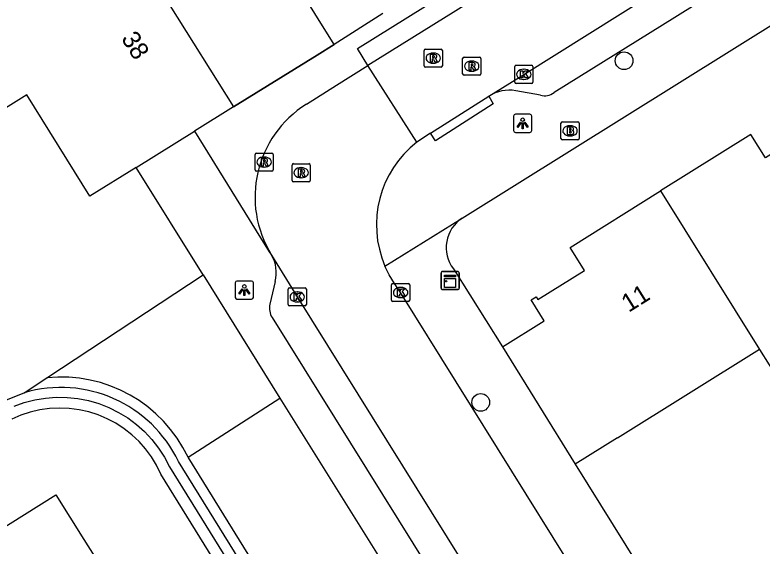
# Model space of a CAD drawing. Extents: x 158838 to 160074, y 386376 to 387776.
# Drawn here: x 159038.51 to 159079.75, y 387026.31 to 387055.6 of the extents above; entities that cross this region are included whole.
import ezdxf

# ---------------------------------------------------------------- set-up
doc = ezdxf.new("R2010")
doc.units = 0
for name, color, linetype in [('IMGEO_Boom', 7, 'Continuous'), ('IMGEO_Brandkraan', 7, 'Continuous'), ('IMGEO_Groenvoorziening', 7, 'Continuous'), ('IMGEO_Hek', 7, 'Continuous'), ('IMGEO_Kast', 7, 'Continuous'), ('IMGEO_Kolk', 7, 'Continuous'), ('IMGEO_Lichtpunt', 7, 'Continuous'), ('IMGEO_Loofbos', 7, 'Continuous'), ('IMGEO_Muur', 7, 'Continuous'), ('IMGEO_Pand', 7, 'Continuous'), ('IMGEO_Pand_nummerreeks', 7, 'Continuous'), ('IMGEO_Rijbaan_lokaal_gesloten', 7, 'Continuous'), ('IMGEO_Rijbaan_lokaal_open', 7, 'Continuous'), ('IMGEO_Rioolput', 7, 'Continuous'), ('IMGEO_Voetpad_open', 7, 'Continuous')]:
    doc.layers.add(name, color=color, linetype=linetype)

msp = doc.modelspace()

# ---------------------------------------------------------------- linework, layer by layer
at = {"layer": 'IMGEO_Boom'}
for centre in [(159072.133, 387053.077), (159064.221, 387034.233)]:
    msp.add_circle(centre, 0.489, dxfattribs=at)
at = {"layer": 'IMGEO_Brandkraan'}
for p, q in [((159068.649, 387048.786), (159068.649, 387049.638)), ((159068.724, 387049.712), (159069.576, 387049.712)), ((159069.137, 387049.492), (159069.162, 387049.492)), ((159069.65, 387049.638), (159069.65, 387048.786)), ((159069.576, 387048.712), (159068.724, 387048.712)), ((159069.16, 387048.932), (159069.135, 387048.932))]:
    msp.add_line(p, q, dxfattribs=at)
for points in [[(159068.649, 387048.786), (159068.649, 387049.638)], [(159068.724, 387049.712), (159069.576, 387049.712)], [(159069.65, 387049.638), (159069.65, 387048.786)], [(159068.997, 387049.412), (159068.997, 387049.012), (159069.21, 387049.012)], [(159069.228, 387049.412), (159068.997, 387049.412)], [(159069.176, 387049.331), (159069.122, 387049.331), (159069.122, 387049.255)], [(159069.122, 387049.255), (159069.175, 387049.255)], [(159069.184, 387049.179), (159069.122, 387049.179), (159069.122, 387049.098)], [(159069.122, 387049.098), (159069.184, 387049.098)], [(159069.576, 387048.712), (159068.724, 387048.712)]]:
    msp.add_lwpolyline(points, dxfattribs=at)
for centre, radius, start, end in [((159068.726, 387049.636), 0.0765, 91.552, 178.448), ((159068.726, 387049.636), 0.0765, 91.552, 178.448), ((159069.574, 387049.636), 0.0765, 1.552, 88.448), ((159069.574, 387049.636), 0.0765, 1.552, 88.448), ((159069.177, 387049.293), 0.0379, 267.8285, 90.9355), ((159069.185, 387049.138), 0.0404, 269.8759, 90.5077), ((159069.216, 387049.263), 0.251, 268.6676, 293.5347), ((159069.232, 387049.267), 0.145, 59.4692, 91.5367), ((159069.257, 387049.314), 0.0922, 285.5137, 58.1501), ((159069.262, 387049.122), 0.105, 301.3115, 78.989), ((159068.726, 387048.788), 0.0765, 181.552, 268.448), ((159068.726, 387048.788), 0.0765, 181.552, 268.448), ((159069.574, 387048.788), 0.0765, 271.552, 358.448), ((159069.574, 387048.788), 0.0765, 271.552, 358.448)]:
    msp.add_arc(centre, radius, start, end, dxfattribs=at)
for centre, major_axis, ratio, start_param, end_param in [((159069.136, 387049.212), (-0.387, 0.002), 0.722429, 4.712389, 7.853982), ((159069.161, 387049.212), (-0.39, 0.002), 0.717154, 1.570796, 4.712389)]:
    msp.add_ellipse(centre, major_axis=major_axis, ratio=ratio, start_param=start_param, end_param=end_param, dxfattribs=at)
at = {"layer": 'IMGEO_Groenvoorziening'}
for points in [[(159040.266, 387035.588), (159048.898, 387041.261)], [(159039.016, 387034.766), (159040.266, 387035.588)], [(159033.552, 387032.261), (159037.206, 387034.045), (159039.016, 387034.766)], [(159038.465, 387034.016), (159039.026, 387034.218), (159039.604, 387034.369), (159040.193, 387034.467), (159040.788, 387034.513), (159041.385, 387034.505), (159041.979, 387034.444), (159042.565, 387034.33), (159043.139, 387034.164), (159043.695, 387033.948), (159044.23, 387033.683), (159044.739, 387033.371), (159045.219, 387033.015), (159045.664, 387032.617), (159046.072, 387032.181), (159046.44, 387031.711), (159046.764, 387031.209), (159047.042, 387030.681), (159066.053, 387000)], [(159048.064, 387031.206), (159053.135, 387034.473)], [(159110.881, 386928.808), (159066.743, 387000), (159047.544, 387030.967)], [(159057.059, 387016.709), (159048.064, 387031.206)]]:
    msp.add_lwpolyline(points, dxfattribs=at)
for centre, radius, start, end in [((159041.075, 387027.898), 7.732, 25.328, 96.0053), ((159041.036, 387027.83), 7.225, 25.739, 106.2375)]:
    msp.add_arc(centre, radius, start, end, dxfattribs=at)
at = {"layer": 'IMGEO_Hek'}
msp.add_lwpolyline([(159039.016, 387034.766), (159040.266, 387035.588)], dxfattribs=at)
at = {"layer": 'IMGEO_Kast'}
for p, q in [((159062.029, 387040.525), (159062.029, 387041.366)), ((159062.029, 387041.366), (159062.029, 387040.525)), ((159062.104, 387041.45), (159062.945, 387041.45)), ((159062.945, 387041.45), (159062.104, 387041.45)), ((159063.029, 387041.375), (159063.029, 387040.534)), ((159063.029, 387040.534), (159063.029, 387041.375)), ((159062.954, 387040.45), (159062.113, 387040.45)), ((159062.113, 387040.45), (159062.954, 387040.45))]:
    msp.add_line(p, q, dxfattribs=at)
for points in [[(159062.224, 387041.24), (159062.824, 387041.24), (159062.824, 387041.155), (159062.224, 387041.155), (159062.224, 387041.24)], [(159062.224, 387041.065), (159062.824, 387041.065), (159062.824, 387040.576), (159062.224, 387040.576), (159062.224, 387041.065)]]:
    msp.add_lwpolyline(points, dxfattribs=at)
msp.add_circle((159062.308, 387040.914), 0.0377, dxfattribs=at)
for centre, start, end in [((159062.107, 387041.372), 92.4484, 184.2845), ((159062.107, 387041.372), 92.4484, 184.2845), ((159062.951, 387041.372), 2.4484, 94.2845), ((159062.951, 387041.372), 2.4484, 94.2845), ((159062.107, 387040.528), 182.4484, 274.2845), ((159062.107, 387040.528), 182.4484, 274.2845), ((159062.951, 387040.528), 272.4484, 4.2845), ((159062.951, 387040.528), 272.4484, 4.2845)]:
    msp.add_arc(centre, 0.0779, start, end, dxfattribs=at)
at = {"layer": 'IMGEO_Kolk'}
for p, q in [((159066.096, 387051.899), (159066.096, 387052.751)), ((159066.171, 387052.825), (159067.023, 387052.825)), ((159067.097, 387052.751), (159067.097, 387051.899)), ((159066.584, 387052.605), (159066.609, 387052.605)), ((159066.607, 387052.045), (159066.582, 387052.045)), ((159067.023, 387051.825), (159066.171, 387051.825)), ((159059.375, 387040.79), (159060.227, 387040.79)), ((159053.595, 387039.623), (159053.595, 387040.475)), ((159053.67, 387040.549), (159054.522, 387040.549)), ((159054.596, 387040.475), (159054.596, 387039.623)), ((159059.3, 387039.864), (159059.3, 387040.716)), ((159059.788, 387040.57), (159059.813, 387040.57)), ((159060.301, 387040.716), (159060.301, 387039.864)), ((159054.083, 387040.329), (159054.108, 387040.329)), ((159059.811, 387040.01), (159059.786, 387040.01)), ((159054.522, 387039.549), (159053.67, 387039.549)), ((159054.106, 387039.769), (159054.081, 387039.769)), ((159060.227, 387039.79), (159059.375, 387039.79))]:
    msp.add_line(p, q, dxfattribs=at)
for points in [[(159066.096, 387051.899), (159066.096, 387052.751)], [(159066.171, 387052.825), (159067.023, 387052.825)], [(159067.097, 387052.751), (159067.097, 387051.899)], [(159066.417, 387052.525), (159066.54, 387052.525), (159066.54, 387052.374), (159066.67, 387052.525), (159066.834, 387052.525), (159066.688, 387052.374), (159066.841, 387052.125), (159066.689, 387052.125), (159066.604, 387052.289), (159066.54, 387052.222), (159066.54, 387052.125), (159066.417, 387052.125), (159066.417, 387052.525)], [(159067.023, 387051.825), (159066.171, 387051.825)], [(159059.375, 387040.79), (159060.227, 387040.79)], [(159053.595, 387039.623), (159053.595, 387040.475)], [(159053.67, 387040.549), (159054.522, 387040.549)], [(159054.596, 387040.475), (159054.596, 387039.623)], [(159059.3, 387039.864), (159059.3, 387040.716)], [(159059.621, 387040.49), (159059.744, 387040.49), (159059.744, 387040.339), (159059.874, 387040.49), (159060.038, 387040.49), (159059.892, 387040.339), (159060.045, 387040.09), (159059.893, 387040.09), (159059.808, 387040.254), (159059.744, 387040.187), (159059.744, 387040.09), (159059.621, 387040.09), (159059.621, 387040.49)], [(159060.301, 387040.716), (159060.301, 387039.864)], [(159053.916, 387040.249), (159054.039, 387040.249), (159054.039, 387040.098), (159054.169, 387040.249), (159054.333, 387040.249), (159054.187, 387040.098), (159054.34, 387039.849), (159054.188, 387039.849), (159054.103, 387040.013), (159054.039, 387039.946), (159054.039, 387039.849), (159053.916, 387039.849), (159053.916, 387040.249)], [(159054.522, 387039.549), (159053.67, 387039.549)], [(159060.227, 387039.79), (159059.375, 387039.79)]]:
    msp.add_lwpolyline(points, dxfattribs=at)
for centre, start, end in [((159066.173, 387052.749), 91.552, 178.448), ((159066.173, 387052.749), 91.552, 178.448), ((159067.021, 387052.749), 1.552, 88.448), ((159067.021, 387052.749), 1.552, 88.448), ((159066.173, 387051.901), 181.552, 268.448), ((159066.173, 387051.901), 181.552, 268.448), ((159067.021, 387051.901), 271.552, 358.448), ((159067.021, 387051.901), 271.552, 358.448), ((159059.377, 387040.714), 91.552, 178.448), ((159059.377, 387040.714), 91.552, 178.448), ((159060.225, 387040.714), 1.552, 88.448), ((159060.225, 387040.714), 1.552, 88.448), ((159053.672, 387040.473), 91.552, 178.448), ((159053.672, 387040.473), 91.552, 178.448), ((159054.52, 387040.473), 1.552, 88.448), ((159054.52, 387040.473), 1.552, 88.448), ((159053.672, 387039.625), 181.552, 268.448), ((159053.672, 387039.625), 181.552, 268.448), ((159054.52, 387039.625), 271.552, 358.448), ((159054.52, 387039.625), 271.552, 358.448), ((159059.377, 387039.866), 181.552, 268.448), ((159059.377, 387039.866), 181.552, 268.448), ((159060.225, 387039.866), 271.552, 358.448), ((159060.225, 387039.866), 271.552, 358.448)]:
    msp.add_arc(centre, 0.0765, start, end, dxfattribs=at)
for centre, major_axis, ratio, start_param, end_param in [((159066.583, 387052.325), (-0.387, 0.002), 0.722429, 4.712389, 7.853982), ((159066.608, 387052.325), (-0.39, 0.002), 0.717154, 1.570796, 4.712389), ((159059.787, 387040.29), (-0.387, 0.002), 0.722429, 4.712389, 7.853982), ((159059.812, 387040.29), (-0.39, 0.002), 0.717154, 1.570796, 4.712389), ((159054.082, 387040.049), (-0.387, 0.002), 0.722429, 4.712389, 7.853982), ((159054.107, 387040.049), (-0.39, 0.002), 0.717154, 1.570796, 4.712389)]:
    msp.add_ellipse(centre, major_axis=major_axis, ratio=ratio, start_param=start_param, end_param=end_param, dxfattribs=at)
at = {"layer": 'IMGEO_Lichtpunt'}
for p, q in [((159066.037, 387050.028), (159066.037, 387049.221)), ((159066.037, 387050.028), (159066.037, 387049.221)), ((159066.939, 387050.123), (159066.131, 387050.123)), ((159066.939, 387050.123), (159066.131, 387050.123)), ((159067.033, 387049.221), (159067.033, 387050.028)), ((159067.033, 387049.221), (159067.033, 387050.028)), ((159066.131, 387049.127), (159066.939, 387049.127)), ((159066.131, 387049.127), (159066.939, 387049.127)), ((159050.674, 387040.83), (159050.674, 387040.023)), ((159050.674, 387040.83), (159050.674, 387040.023)), ((159051.576, 387040.925), (159050.768, 387040.925)), ((159051.576, 387040.925), (159050.768, 387040.925)), ((159051.67, 387040.023), (159051.67, 387040.83)), ((159051.67, 387040.023), (159051.67, 387040.83)), ((159050.768, 387039.929), (159051.576, 387039.929)), ((159050.768, 387039.929), (159051.576, 387039.929))]:
    msp.add_line(p, q, dxfattribs=at)
for points in [[(159066.411, 387049.692), (159066.45, 387049.664), (159066.262, 387049.402), (159066.224, 387049.429), (159066.411, 387049.692)], [(159066.513, 387049.644), (159066.56, 387049.644), (159066.56, 387049.322), (159066.513, 387049.322), (159066.513, 387049.644)], [(159066.623, 387049.664), (159066.661, 387049.691), (159066.848, 387049.429), (159066.809, 387049.401), (159066.623, 387049.664)], [(159051.048, 387040.494), (159051.087, 387040.466), (159050.899, 387040.204), (159050.861, 387040.231), (159051.048, 387040.494)], [(159051.15, 387040.446), (159051.197, 387040.446), (159051.197, 387040.124), (159051.15, 387040.124), (159051.15, 387040.446)], [(159051.26, 387040.466), (159051.298, 387040.493), (159051.485, 387040.231), (159051.446, 387040.203), (159051.26, 387040.466)]]:
    msp.add_lwpolyline(points, dxfattribs=at)
for centre in [(159066.536, 387049.826), (159051.173, 387040.628)]:
    msp.add_circle(centre, 0.0994, dxfattribs=at)
for centre, start, end in [((159066.131, 387050.028), 90, 180), ((159066.131, 387050.028), 90, 180), ((159066.939, 387050.028), 0, 90), ((159066.939, 387050.028), 0, 90), ((159066.131, 387049.221), 180, 270), ((159066.131, 387049.221), 180, 270), ((159066.939, 387049.221), 270, 0), ((159066.939, 387049.221), 270, 360), ((159050.768, 387040.83), 90, 180), ((159050.768, 387040.83), 90, 180), ((159051.576, 387040.83), 0, 90), ((159051.576, 387040.83), 0, 90), ((159050.768, 387040.023), 180, 270), ((159050.768, 387040.023), 180, 270), ((159051.576, 387040.023), 270, 0), ((159051.576, 387040.023), 270, 360)]:
    msp.add_arc(centre, 0.0946, start, end, dxfattribs=at)
at = {"layer": 'IMGEO_Loofbos'}
for points in [[(159065.319, 387000), (159046.571, 387030.271), (159046.331, 387030.76), (159046.048, 387031.225), (159045.724, 387031.663), (159045.363, 387032.07), (159044.967, 387032.444), (159044.539, 387032.78), (159044.082, 387033.078), (159043.601, 387033.333), (159043.099, 387033.544), (159042.581, 387033.709), (159042.049, 387033.828), (159041.509, 387033.898), (159040.965, 387033.92), (159040.421, 387033.893), (159039.882, 387033.818), (159039.352, 387033.695), (159038.834, 387033.525), (159038.334, 387033.309)], [(159027.668, 387025.411), (159031.623, 387024.617), (159033.066, 387024.328), (159037.285, 387026.957), (159040.771, 387029.129), (159042.317, 387026.665), (159042.882, 387025.766), (159059.05, 387000), (159105.278, 386926.65)]]:
    msp.add_lwpolyline(points, dxfattribs=at)
at = {"layer": 'IMGEO_Muur'}
for points in [[(159055.192, 387053.386), (159056.14, 387053.974)], [(159050.577, 387050.525), (159055.192, 387053.386)], [(159069.441, 387030.819), (159076.524, 387019.468)]]:
    msp.add_lwpolyline(points, dxfattribs=at)
at = {"layer": 'IMGEO_Pand'}
for points in [[(159044.387, 387060.389), (159045.439, 387061.047), (159048.113, 387056.775), (159047.067, 387056.119), (159050.577, 387050.525)], [(159045.198, 387047.189), (159042.642, 387045.603), (159039.161, 387051.19), (159027.496, 387043.921), (159024.821, 387048.202), (159036.538, 387055.521)], [(159050.577, 387050.525), (159048.428, 387049.192)], [(159045.198, 387047.189), (159048.428, 387049.192)], [(159082.578, 387049.382), (159079.934, 387047.727), (159079.133, 387049.006), (159074.14, 387045.892)], [(159065.419, 387037.291), (159067.725, 387038.732), (159067.005, 387039.886), (159067.275, 387040.054), (159067.37, 387039.902), (159069.951, 387041.51), (159069.158, 387042.784), (159074.14, 387045.892)], [(159074.14, 387045.892), (159079.6, 387037.141)], [(159079.6, 387037.141), (159081.208, 387034.61), (159088.84, 387039.38), (159087.251, 387041.923)], [(159065.419, 387037.291), (159069.441, 387030.819)], [(159079.6, 387037.141), (159071.774, 387032.25), (159071.762, 387032.269), (159069.441, 387030.819)]]:
    msp.add_lwpolyline(points, dxfattribs=at)
at = {"layer": 'IMGEO_Rijbaan_lokaal_gesloten'}
for points in [[(159054.603, 387050.681), (159056.255, 387051.72), (159057.993, 387052.813)], [(159060.695, 387048.588), (159057.993, 387052.813)], [(159052.677, 387042.36), (159054.093, 387040.05), (159064.841, 387022.833), (159075.554, 387005.639), (159079.076, 387000), (159097.478, 386970.538), (159108.751, 386952.473), (159118.667, 386936.572)], [(159074.471, 387016.785), (159069.014, 387025.517), (159059.796, 387040.289), (159059.457, 387040.794), (159059.172, 387041.262), (159058.932, 387041.754)]]:
    msp.add_lwpolyline(points, dxfattribs=at)
for centre, radius, start, end in [((159057.805, 387045.556), 6.043, 121.9995, 211.9359), ((159064.237, 387044.03), 5.773, 127.8497, 203.2194)]:
    msp.add_arc(centre, radius, start, end, dxfattribs=at)
at = {"layer": 'IMGEO_Rijbaan_lokaal_open'}
for points in [[(159064.66, 387051.128), (159066.593, 387052.325), (159084.528, 387063.55), (159103.151, 387075.188), (159110.593, 387079.859)], [(159066.482, 387058.108), (159057.993, 387052.813)], [(159061.454, 387049.086), (159064.66, 387051.128)], [(159061.454, 387049.086), (159060.695, 387048.588)]]:
    msp.add_lwpolyline(points, dxfattribs=at)
at = {"layer": 'IMGEO_Rioolput'}
for p, q in [((159061.101, 387052.794), (159061.101, 387053.646)), ((159061.176, 387053.72), (159062.028, 387053.72)), ((159062.102, 387053.646), (159062.102, 387052.794)), ((159061.589, 387053.5), (159061.614, 387053.5)), ((159063.223, 387052.351), (159063.223, 387053.203)), ((159063.298, 387053.277), (159064.15, 387053.277)), ((159064.224, 387053.203), (159064.224, 387052.351)), ((159062.028, 387052.72), (159061.176, 387052.72)), ((159061.612, 387052.94), (159061.587, 387052.94)), ((159063.711, 387053.057), (159063.736, 387053.057)), ((159063.734, 387052.497), (159063.709, 387052.497)), ((159064.15, 387052.277), (159063.298, 387052.277)), ((159051.762, 387047.061), (159051.762, 387047.913)), ((159051.837, 387047.987), (159052.689, 387047.987)), ((159052.25, 387047.767), (159052.275, 387047.767)), ((159052.763, 387047.913), (159052.763, 387047.061)), ((159053.883, 387047.399), (159054.735, 387047.399)), ((159052.689, 387046.987), (159051.837, 387046.987)), ((159052.273, 387047.207), (159052.248, 387047.207)), ((159053.808, 387046.473), (159053.808, 387047.325)), ((159054.296, 387047.179), (159054.321, 387047.179)), ((159054.809, 387047.325), (159054.809, 387046.473)), ((159054.319, 387046.619), (159054.294, 387046.619)), ((159054.735, 387046.399), (159053.883, 387046.399))]:
    msp.add_line(p, q, dxfattribs=at)
for points in [[(159061.101, 387052.794), (159061.101, 387053.646)], [(159061.176, 387053.72), (159062.028, 387053.72)], [(159062.102, 387053.646), (159062.102, 387052.794)], [(159061.69, 387053.418), (159061.438, 387053.42), (159061.438, 387053.02)], [(159061.438, 387053.02), (159061.562, 387053.02), (159061.562, 387053.182), (159061.573, 387053.182)], [(159061.616, 387053.339), (159061.562, 387053.339), (159061.562, 387053.258)], [(159061.562, 387053.258), (159061.614, 387053.258)], [(159061.62, 387053.153), (159061.691, 387053.02), (159061.831, 387053.02), (159061.766, 387053.146)], [(159063.223, 387052.351), (159063.223, 387053.203)], [(159063.298, 387053.277), (159064.15, 387053.277)], [(159064.224, 387053.203), (159064.224, 387052.351)], [(159062.028, 387052.72), (159061.176, 387052.72)], [(159063.812, 387052.975), (159063.56, 387052.977), (159063.56, 387052.577)], [(159063.56, 387052.577), (159063.684, 387052.577), (159063.684, 387052.739), (159063.695, 387052.739)], [(159063.738, 387052.896), (159063.684, 387052.896), (159063.684, 387052.815)], [(159063.684, 387052.815), (159063.736, 387052.815)], [(159063.742, 387052.71), (159063.813, 387052.577), (159063.953, 387052.577), (159063.888, 387052.703)], [(159064.15, 387052.277), (159063.298, 387052.277)], [(159051.762, 387047.061), (159051.762, 387047.913)], [(159051.837, 387047.987), (159052.689, 387047.987)], [(159052.763, 387047.913), (159052.763, 387047.061)], [(159052.351, 387047.685), (159052.099, 387047.687), (159052.099, 387047.287)], [(159052.099, 387047.287), (159052.223, 387047.287), (159052.223, 387047.449), (159052.234, 387047.449)], [(159052.277, 387047.606), (159052.223, 387047.606), (159052.223, 387047.525)], [(159052.223, 387047.525), (159052.275, 387047.525)], [(159052.281, 387047.42), (159052.352, 387047.287), (159052.492, 387047.287), (159052.427, 387047.413)], [(159053.883, 387047.399), (159054.735, 387047.399)], [(159052.689, 387046.987), (159051.837, 387046.987)], [(159053.808, 387046.473), (159053.808, 387047.325)], [(159054.397, 387047.097), (159054.145, 387047.099), (159054.145, 387046.699)], [(159054.323, 387047.018), (159054.269, 387047.018), (159054.269, 387046.937)], [(159054.809, 387047.325), (159054.809, 387046.473)], [(159054.145, 387046.699), (159054.269, 387046.699), (159054.269, 387046.861), (159054.28, 387046.861)], [(159054.269, 387046.937), (159054.321, 387046.937)], [(159054.327, 387046.832), (159054.398, 387046.699), (159054.538, 387046.699), (159054.473, 387046.825)], [(159054.735, 387046.399), (159053.883, 387046.399)]]:
    msp.add_lwpolyline(points, dxfattribs=at)
for centre, radius, start, end in [((159061.178, 387053.644), 0.0765, 91.552, 178.448), ((159061.178, 387053.644), 0.0765, 91.552, 178.448), ((159062.026, 387053.644), 0.0765, 1.552, 88.448), ((159062.026, 387053.644), 0.0765, 1.552, 88.448), ((159061.572, 387053.129), 0.0533, 26.0293, 88.6989), ((159061.598, 387053.447), 0.19, 274.7715, 282.9687), ((159061.622, 387053.243), 0.0964, 77.0061, 93.1865), ((159061.636, 387053.3), 0.0378, 276.6634, 79.6772), ((159061.689, 387053.308), 0.109, 350.3612, 89.416), ((159061.687, 387053.308), 0.112, 277.5842, 350.9817), ((159061.671, 387053.093), 0.108, 29.5134, 73.7905), ((159063.3, 387053.201), 0.0765, 91.552, 178.448), ((159063.3, 387053.201), 0.0765, 91.552, 178.448), ((159064.148, 387053.201), 0.0765, 1.552, 88.448), ((159064.148, 387053.201), 0.0765, 1.552, 88.448), ((159061.178, 387052.796), 0.0765, 181.552, 268.448), ((159061.178, 387052.796), 0.0765, 181.552, 268.448), ((159062.026, 387052.796), 0.0765, 271.552, 358.448), ((159062.026, 387052.796), 0.0765, 271.552, 358.448), ((159063.694, 387052.686), 0.0533, 26.0293, 88.6989), ((159063.72, 387053.004), 0.19, 274.7715, 282.9687), ((159063.744, 387052.8), 0.0964, 77.0061, 93.1865), ((159063.758, 387052.857), 0.0378, 276.6634, 79.6772), ((159063.811, 387052.865), 0.109, 350.3612, 89.416), ((159063.809, 387052.865), 0.112, 277.5842, 350.9817), ((159063.793, 387052.65), 0.108, 29.5134, 73.7905), ((159063.3, 387052.353), 0.0765, 181.552, 268.448), ((159063.3, 387052.353), 0.0765, 181.552, 268.448), ((159064.148, 387052.353), 0.0765, 271.552, 358.448), ((159064.148, 387052.353), 0.0765, 271.552, 358.448), ((159051.839, 387047.911), 0.0765, 91.552, 178.448), ((159051.839, 387047.911), 0.0765, 91.552, 178.448), ((159052.687, 387047.911), 0.0765, 1.552, 88.448), ((159052.687, 387047.911), 0.0765, 1.552, 88.448), ((159052.233, 387047.396), 0.0533, 26.0293, 88.6989), ((159052.259, 387047.714), 0.19, 274.7715, 282.9687), ((159052.283, 387047.51), 0.0964, 77.0061, 93.1865), ((159052.297, 387047.567), 0.0378, 276.6634, 79.6772), ((159052.35, 387047.575), 0.109, 350.3612, 89.416), ((159052.348, 387047.575), 0.112, 277.5842, 350.9817), ((159052.332, 387047.36), 0.108, 29.5134, 73.7905), ((159053.885, 387047.323), 0.0765, 91.552, 178.448), ((159053.885, 387047.323), 0.0765, 91.552, 178.448), ((159054.733, 387047.323), 0.0765, 1.552, 88.448), ((159054.733, 387047.323), 0.0765, 1.552, 88.448), ((159051.839, 387047.063), 0.0765, 181.552, 268.448), ((159051.839, 387047.063), 0.0765, 181.552, 268.448), ((159052.687, 387047.063), 0.0765, 271.552, 358.448), ((159052.687, 387047.063), 0.0765, 271.552, 358.448), ((159054.305, 387047.126), 0.19, 274.7715, 282.9687), ((159054.329, 387046.922), 0.0964, 77.0061, 93.1865), ((159054.343, 387046.979), 0.0378, 276.6634, 79.6772), ((159054.396, 387046.987), 0.109, 350.3612, 89.416), ((159054.394, 387046.987), 0.112, 277.5842, 350.9817), ((159054.279, 387046.808), 0.0533, 26.0293, 88.6989), ((159054.378, 387046.772), 0.108, 29.5134, 73.7905), ((159053.885, 387046.475), 0.0765, 181.552, 268.448), ((159053.885, 387046.475), 0.0765, 181.552, 268.448), ((159054.733, 387046.475), 0.0765, 271.552, 358.448), ((159054.733, 387046.475), 0.0765, 271.552, 358.448)]:
    msp.add_arc(centre, radius, start, end, dxfattribs=at)
for centre, major_axis, ratio, start_param, end_param in [((159061.588, 387053.22), (-0.387, 0.002), 0.722429, 4.712389, 7.853982), ((159061.613, 387053.22), (-0.39, 0.002), 0.717154, 1.570796, 4.712389), ((159063.71, 387052.777), (-0.387, 0.002), 0.722429, 4.712389, 7.853982), ((159063.735, 387052.777), (-0.39, 0.002), 0.717154, 1.570796, 4.712389), ((159052.249, 387047.487), (-0.387, 0.002), 0.722429, 4.712389, 7.853982), ((159052.274, 387047.487), (-0.39, 0.002), 0.717154, 1.570796, 4.712389), ((159054.295, 387046.899), (-0.387, 0.002), 0.722429, 4.712389, 7.853982), ((159054.32, 387046.899), (-0.39, 0.002), 0.717154, 1.570796, 4.712389)]:
    msp.add_ellipse(centre, major_axis=major_axis, ratio=ratio, start_param=start_param, end_param=end_param, dxfattribs=at)
at = {"layer": 'IMGEO_Voetpad_open'}
for points in [[(159056.14, 387053.974), (159008.415, 387130.408), (159005.915, 387134.425)], [(159108.9, 387076.666), (159108.343, 387076.314), (159105.146, 387074.32), (159095.791, 387068.486), (159090.042, 387064.897), (159080.693, 387059.061), (159074.93, 387055.455), (159068.268, 387051.318)], [(159063.193, 387044.393), (159110.736, 387074.06)], [(159057.993, 387052.813), (159057.411, 387053.746), (159065.9, 387059.041), (159066.482, 387058.108)], [(159058.826, 387055.683), (159056.14, 387053.974)], [(159056.14, 387053.974), (159055.192, 387053.386), (159050.577, 387050.525)], [(159064.66, 387051.128), (159064.902, 387050.691), (159061.722, 387048.665), (159061.454, 387049.086)], [(159067.52, 387051.17), (159066.154, 387051.423)], [(159048.428, 387049.192), (159052.552, 387042.529), (159052.677, 387042.36)], [(159048.898, 387041.261), (159045.198, 387047.189)], [(159058.932, 387041.754), (159063.193, 387044.393)], [(159062.71, 387041.605), (159065.419, 387037.291)], [(159048.898, 387041.261), (159053.135, 387034.473)], [(159052.877, 387040.907), (159052.585, 387039.648)], [(159052.701, 387038.906), (159076.971, 387000)], [(159053.135, 387034.473), (159062.139, 387020.048)], [(159069.441, 387030.819), (159076.524, 387019.468), (159125.496, 386940.988)]]:
    msp.add_lwpolyline(points, dxfattribs=at)
for centre, radius, start, end in [((159065.807, 387049.251), 2.199, 80.9146, 121.4248), ((159067.731, 387052.067), 0.922, 256.753, 305.631), ((159064.253, 387042.773), 1.936, 123.2138, 217.1292), ((159050.989, 387041.387), 1.948, 345.7193, 29.9553), ((159053.577, 387039.423), 1.017, 167.222, 210.5488)]:
    msp.add_arc(centre, radius, start, end, dxfattribs=at)

# ---------------------------------------------------------------- texts
at = {"layer": 'IMGEO_Pand_nummerreeks'}
for s, rotation, p in [('38', 302.0052, (159044.349, 387054.301)), ('11', 32.0045, (159072.386, 387039.169))]:
    msp.add_text(s, height=1, rotation=rotation, dxfattribs=at).set_placement(p)

doc.saveas('drawing.dxf')
